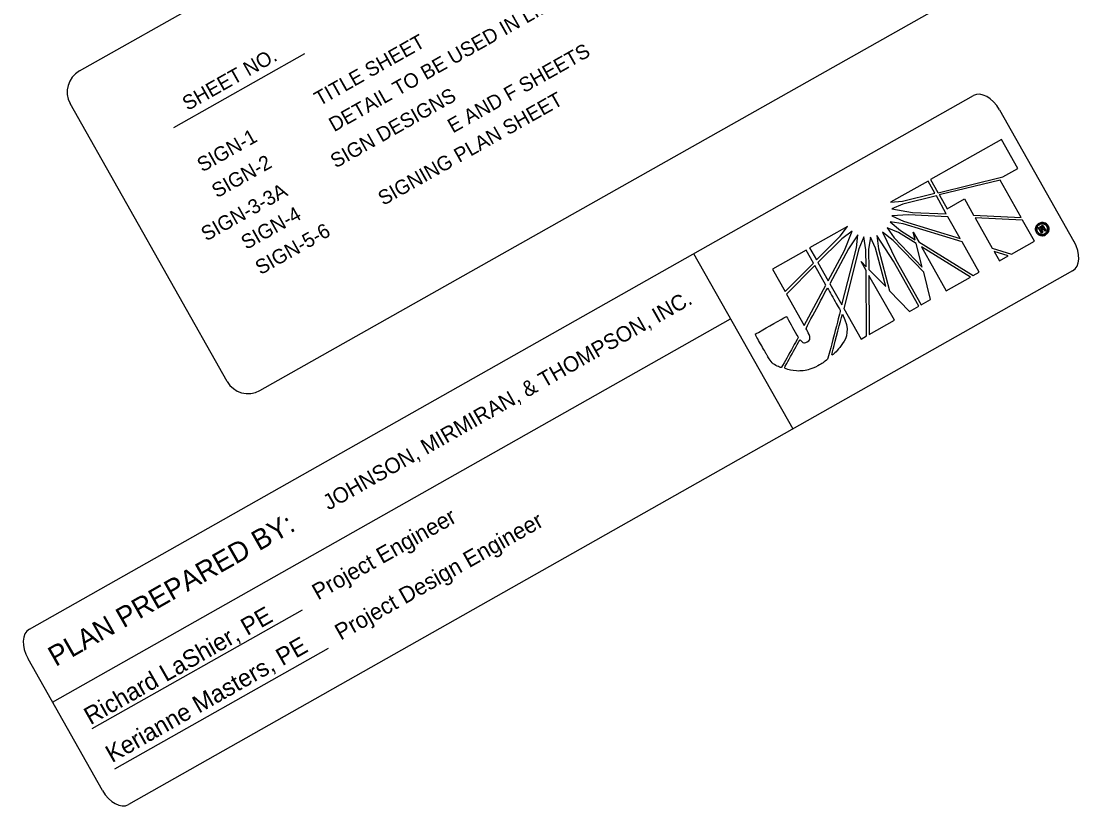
# Model space of a CAD drawing. Extents: x 2217708 to 2219063, y 217550 to 219141.
# Drawn here: x 2218577.8 to 2219063.3, y 217897.3 to 218258.3 of the extents above; entities that cross this region are included whole.
import ezdxf

# ---------------------------------------------------------------- set-up
doc = ezdxf.new("R2010")
doc.units = 0
doc.layers.add('Default', color=7, linetype='Continuous')
doc.layers.add('Sheet Title CELL', color=7, linetype='Continuous')

msp = doc.modelspace()

# ---------------------------------------------------------------- linework, layer by layer
at = {"layer": 'Default'}
for p, q in [((2218647.82, 218209.63), (2218707.74, 218243.47)), ((2218581.59, 217979.54), (2219014.14, 218224.21)), ((2219026.06, 218217.75), (2219060.22, 218157.38)), ((2219027.03, 218204.14), (2218994.51, 218185.75)), ((2219034.56, 218190.81), (2219027.03, 218204.14)), ((2218997.99, 218179.6), (2219027.65, 218186.9)), ((2219027.65, 218186.9), (2219034.56, 218190.81)), ((2218993.36, 218185), (2218976.16, 218175.37)), ((2218996.5, 218179.43), (2218993.36, 218185)), ((2218994.51, 218185.75), (2218997.89, 218179.78)), ((2219026.35, 218185.39), (2218998.51, 218178.68)), ((2219036, 218168.31), (2219026.35, 218185.39)), ((2218981.65, 218175.79), (2218996.5, 218179.43)), ((2218997.17, 218178.26), (2218981.85, 218174.42)), ((2219001.7, 218170.01), (2218997.17, 218178.26)), ((2218997.89, 218179.78), (2218997.99, 218179.6)), ((2218998.51, 218178.68), (2218998.57, 218178.58)), ((2218998.57, 218178.58), (2219002.09, 218172.35)), ((2218976.16, 218175.37), (2218981.65, 218175.79)), ((2218981.85, 218174.42), (2218976.73, 218172.33)), ((2218976.73, 218172.33), (2218986.22, 218170.69)), ((2219002.09, 218172.35), (2219010.03, 218176.84)), ((2219010.03, 218176.84), (2219014.23, 218169.41)), ((2218984.4, 218169.56), (2218976.74, 218169.17)), ((2218976.74, 218169.17), (2218982.13, 218166.59)), ((2219002.47, 218168.63), (2218984.4, 218169.56)), ((2218986.22, 218170.69), (2219001.7, 218170.01)), ((2219008.07, 218158.72), (2219002.47, 218168.63)), ((2219014.23, 218169.41), (2219036, 218168.31)), ((2219014.95, 218168.13), (2219022.77, 218154.3)), ((2219036.68, 218167.11), (2219014.95, 218168.13)), ((2218956.45, 218164.23), (2218939.04, 218154.39)), ((2218953.12, 218159.76), (2218956.45, 218164.23)), ((2218974.56, 218163.66), (2218977.87, 218159)), ((2218979.77, 218161.42), (2218974.56, 218163.66)), ((2218975.98, 218166.28), (2218980.67, 218162.39)), ((2218981.88, 218165.44), (2218975.98, 218166.28)), ((2219008.98, 218157.12), (2218981.88, 218165.44)), ((2218982.13, 218166.59), (2219008.07, 218158.72)), ((2219042.1, 218157.52), (2219036.68, 218167.11)), ((2219044.02, 218163.65), (2219044.98, 218164.19)), ((2219045.35, 218161.28), (2219044.02, 218163.65)), ((2219044.19, 218165.59), (2219044.47, 218165.09)), ((2219044.47, 218165.09), (2219044.19, 218165.59)), ((2219045.24, 218163.74), (2219044.81, 218163.5)), ((2219044.81, 218163.5), (2219045.12, 218162.94)), ((2219044.98, 218164.19), (2219045.13, 218164.28)), ((2219044.98, 218164.19), (2219045.24, 218163.74)), ((2219045.24, 218163.74), (2219044.98, 218164.19)), ((2219045.12, 218162.94), (2219045.55, 218163.18)), ((2219045.3, 218163.78), (2219045.24, 218163.74)), ((2219045.8, 218162.75), (2219045.37, 218162.51)), ((2219045.37, 218162.51), (2219045.89, 218161.58)), ((2219045.55, 218163.18), (2219045.58, 218163.19)), ((2219045.55, 218163.18), (2219045.8, 218162.75)), ((2219045.8, 218162.75), (2219045.55, 218163.18)), ((2219045.82, 218162.76), (2219045.8, 218162.75)), ((2218942.18, 218148.85), (2218953.12, 218159.76)), ((2218953.8, 218158.56), (2218942.85, 218147.65)), ((2218958.51, 218162.03), (2218953.8, 218158.56)), ((2218955.05, 218153.2), (2218958.51, 218162.03)), ((2218961.14, 218160.35), (2218956.93, 218154.03)), ((2218960.52, 218154.47), (2218961.14, 218160.35)), ((2218963.98, 218159.5), (2218961.66, 218154.01)), ((2218964.89, 218153.48), (2218963.98, 218159.5)), ((2218966.98, 218159.37), (2218966.14, 218153.71)), ((2218969.25, 218154.35), (2218966.98, 218159.37)), ((2218977.49, 218148.3), (2218969.92, 218160.13)), ((2218969.92, 218160.13), (2218970.61, 218153.98)), ((2218972.48, 218161.57), (2218978.58, 218148.92)), ((2218977.32, 218157.77), (2218972.48, 218161.57)), ((2218991.36, 218143.31), (2218977.32, 218157.77)), ((2218977.87, 218159), (2218990.71, 218145.64)), ((2218987.88, 218156.43), (2218979.77, 218161.42)), ((2218980.67, 218162.39), (2218987.46, 218158.12)), ((2218987.46, 218158.12), (2218986.52, 218161.63)), ((2218986.52, 218161.63), (2218989.08, 218157.11)), ((2219045.89, 218161.58), (2219045.35, 218161.28)), ((2219046.84, 218160.9), (2219046.86, 218160.92)), ((2219046.84, 218160.9), (2219047.13, 218160.39)), ((2219047.13, 218160.39), (2219046.84, 218160.9)), ((2219047.16, 218160.4), (2219047.13, 218160.39)), ((2218937.48, 218153.4), (2218922.01, 218144.66)), ((2218940.86, 218147.43), (2218937.48, 218153.4)), ((2218939.04, 218154.39), (2218942.18, 218148.85)), ((2218947.59, 218139.28), (2218955.05, 218153.2)), ((2218956.93, 218154.03), (2218948.35, 218137.93)), ((2218953.81, 218128.28), (2218960.52, 218154.47)), ((2218961.66, 218154.01), (2218954.73, 218126.64)), ((2218964.99, 218145.75), (2218964.89, 218153.48)), ((2218966.14, 218153.71), (2218966.24, 218144.54)), ((2218973.97, 218136.65), (2218969.25, 218154.35)), ((2218970.61, 218153.98), (2218975.69, 218134.79)), ((2218990.71, 218145.64), (2218987.88, 218156.43)), ((2218989.08, 218157.11), (2219014.1, 218141.69)), ((2219012.78, 218141.04), (2218990.33, 218154.89)), ((2218990.33, 218154.89), (2219001.71, 218134.78)), ((2219016.83, 218143.23), (2219008.98, 218157.12)), ((2219022.77, 218154.3), (2219031.61, 218151.59)), ((2219030.08, 218150.72), (2219023.62, 218152.79)), ((2219023.62, 218152.79), (2219026.08, 218148.45)), ((2219031.61, 218151.59), (2219042.1, 218157.52)), ((2218931.48, 218071.35), (2218886.01, 218151.73)), ((2218964.94, 218144.04), (2218962.63, 218148.12)), ((2218962.63, 218148.12), (2218964.99, 218145.75)), ((2218989.15, 218127.68), (2218977.49, 218148.3)), ((2218978.58, 218148.92), (2218990.25, 218128.3)), ((2219026.08, 218148.45), (2219030.08, 218150.72)), ((2219059.61, 218143.83), (2218627.06, 217899.16)), ((2218922.01, 218144.66), (2218927.81, 218134.4)), ((2218927.81, 218134.4), (2218940.86, 218147.43)), ((2218941.49, 218146.31), (2218928.48, 218133.22)), ((2218946.56, 218137.35), (2218941.49, 218146.31)), ((2218942.85, 218147.65), (2218947.59, 218139.28)), ((2218965.22, 218114.05), (2218964.94, 218144.04)), ((2218966.24, 218144.54), (2218973.97, 218136.65)), ((2218994.53, 218130.72), (2218991.36, 218143.31)), ((2219014.1, 218141.69), (2219016.83, 218143.23)), ((2218977.96, 218121.25), (2218966.2, 218141.82)), ((2218966.2, 218141.82), (2218966.42, 218114.73)), ((2219001.71, 218134.78), (2219012.78, 218141.04)), ((2218936.63, 218118.8), (2218946.56, 218137.35)), ((2218948.35, 218137.93), (2218953.81, 218128.28)), ((2218975.69, 218134.79), (2218984.91, 218125.28)), ((2218928.48, 218133.22), (2218936.63, 218118.8)), ((2218990.25, 218128.3), (2218994.53, 218130.72)), ((2218954.73, 218126.64), (2218962.67, 218112.6)), ((2218984.91, 218125.28), (2218989.15, 218127.68)), ((2218592.22, 217946.09), (2218902.88, 218121.91)), ((2218966.42, 218114.73), (2218977.96, 218121.25)), ((2218962.67, 218112.6), (2218965.22, 218114.05)), ((2218610.35, 217934.06), (2218706.7, 217988.48)), ((2218620.77, 217915.61), (2218718.69, 217970.9)), ((2218615.11, 217905.67), (2218580.95, 217966.04))]:
    msp.add_line(p, q, dxfattribs=at)
for points in [[(2219027.03, 218204.14), (2218994.51, 218185.75), (2218997.89, 218179.78), (2218997.99, 218179.6), (2219027.65, 218186.9), (2219034.56, 218190.81), (2219027.03, 218204.14)], [(2218981.65, 218175.79), (2218996.5, 218179.43), (2218993.36, 218185), (2218976.16, 218175.37), (2218981.65, 218175.79)], [(2218998.51, 218178.68), (2218998.57, 218178.58), (2219002.09, 218172.35), (2219010.03, 218176.84), (2219014.23, 218169.41), (2219036, 218168.31), (2219026.35, 218185.39), (2218998.51, 218178.68)], [(2218976.73, 218172.33), (2218986.22, 218170.69), (2219001.7, 218170.01), (2218997.17, 218178.26), (2218981.85, 218174.42), (2218976.73, 218172.33)], [(2218976.74, 218169.17), (2218982.13, 218166.59), (2219008.07, 218158.72), (2219002.47, 218168.63), (2218984.4, 218169.56), (2218976.74, 218169.17)], [(2219014.95, 218168.13), (2219022.77, 218154.3), (2219031.61, 218151.59), (2219042.1, 218157.52), (2219036.68, 218167.11), (2219014.95, 218168.13), (2219014.95, 218168.13)], [(2218953.12, 218159.76), (2218956.45, 218164.23), (2218939.04, 218154.39), (2218942.18, 218148.85), (2218953.12, 218159.76)], [(2218974.56, 218163.66), (2218977.87, 218159), (2218990.71, 218145.64), (2218987.88, 218156.43), (2218979.77, 218161.42), (2218974.56, 218163.66)], [(2218975.98, 218166.28), (2218980.67, 218162.39), (2218987.46, 218158.12), (2218986.52, 218161.63), (2218989.08, 218157.11), (2219014.1, 218141.69), (2219016.83, 218143.23), (2219008.98, 218157.12), (2218981.88, 218165.44), (2218975.98, 218166.28)], [(2219044.98, 218164.19), (2219044.02, 218163.65), (2219045.35, 218161.28), (2219045.89, 218161.58), (2219045.37, 218162.51), (2219045.8, 218162.75), (2219045.55, 218163.18), (2219045.12, 218162.94), (2219044.81, 218163.5), (2219045.24, 218163.74), (2219044.98, 218164.19)], [(2219047.04, 218162.97), (2219047.11, 218162.84), (2219047.18, 218162.77), (2219047.23, 218162.68), (2219047.44, 218162.46), (2219046.94, 218162.18)], [(2218942.85, 218147.65), (2218947.59, 218139.28), (2218955.05, 218153.2), (2218958.51, 218162.03), (2218953.8, 218158.56), (2218942.85, 218147.65)], [(2218948.35, 218137.93), (2218953.81, 218128.28), (2218960.52, 218154.47), (2218961.14, 218160.35), (2218956.93, 218154.03), (2218948.35, 218137.93)], [(2218963.98, 218159.5), (2218961.66, 218154.01), (2218954.73, 218126.64), (2218962.67, 218112.6), (2218965.22, 218114.05), (2218964.94, 218144.04), (2218962.63, 218148.12), (2218964.99, 218145.75), (2218964.89, 218153.48), (2218963.98, 218159.5)], [(2218966.98, 218159.37), (2218966.14, 218153.71), (2218966.24, 218144.54), (2218973.97, 218136.65), (2218969.25, 218154.35), (2218966.98, 218159.37)], [(2218970.61, 218153.98), (2218975.69, 218134.79), (2218984.91, 218125.28), (2218989.15, 218127.68), (2218977.49, 218148.3), (2218969.92, 218160.13), (2218970.61, 218153.98)], [(2218972.48, 218161.57), (2218978.58, 218148.92), (2218990.25, 218128.3), (2218994.53, 218130.72), (2218991.36, 218143.31), (2218977.32, 218157.77), (2218972.48, 218161.57)], [(2218927.81, 218134.4), (2218940.86, 218147.43), (2218937.48, 218153.4), (2218922.01, 218144.66), (2218927.81, 218134.4)], [(2219001.71, 218134.78), (2219012.78, 218141.04), (2218990.33, 218154.89), (2219001.71, 218134.78)], [(2219026.08, 218148.45), (2219026.08, 218148.45), (2219030.08, 218150.72), (2219023.62, 218152.79), (2219026.08, 218148.45)], [(2218936.63, 218118.8), (2218946.56, 218137.35), (2218941.49, 218146.31), (2218928.48, 218133.22), (2218936.63, 218118.8)], [(2218966.42, 218114.73), (2218977.96, 218121.25), (2218966.2, 218141.82), (2218966.42, 218114.73)]]:
    msp.add_lwpolyline(points, dxfattribs=at)
for centre, major_axis, start_param, end_param in [((2219019.8, 218214.2), (-5.65, 10.01), 4.713091, 6.283887), ((2219053.96, 218153.83), (5.65, -10.01), 0.000702, 1.571498), ((2218587.22, 217969.59), (-5.65, 10.01), 0.000702, 1.571498), ((2218621.38, 217909.21), (5.65, -10.01), 4.713091, 6.283887)]:
    msp.add_ellipse(centre, major_axis=major_axis, ratio=0.62659, start_param=start_param, end_param=end_param, dxfattribs=at)
for points, degree in [([(2219047.13, 218160.39), (2219046.43, 218159.99), (2219045.66, 218159.89), (2219044.85, 218160.12), (2219044.05, 218160.32), (2219043.44, 218160.8), (2219043.03, 218161.53), (2219042.62, 218162.26), (2219042.52, 218163.03), (2219042.77, 218163.79), (2219043.01, 218164.58), (2219043.46, 218165.18), (2219044.19, 218165.59), (2219044.19, 218165.59), (2219044.47, 218165.09), (2219044.47, 218165.09), (2219043.89, 218164.77), (2219043.51, 218164.29), (2219043.32, 218163.68), (2219043.14, 218163.04), (2219043.22, 218162.4), (2219043.54, 218161.82), (2219043.87, 218161.24), (2219044.38, 218160.84), (2219045.02, 218160.67), (2219045.66, 218160.49), (2219046.26, 218160.57), (2219046.84, 218160.9), (2219046.84, 218160.9), (2219047.13, 218160.39), (2219047.13, 218160.39), (2219047.13, 218160.39), (2219047.13, 218160.39), (2219047.13, 218160.39)], 3), ([(2219047.13, 218160.39), (2219046.43, 218159.99), (2219045.66, 218159.89), (2219044.85, 218160.12), (2219044.05, 218160.32), (2219043.44, 218160.8), (2219043.03, 218161.53), (2219042.62, 218162.26), (2219042.52, 218163.03), (2219042.77, 218163.79), (2219043.01, 218164.58), (2219043.46, 218165.18), (2219044.19, 218165.59)], 3), ([(2219044.47, 218165.09), (2219043.89, 218164.77), (2219043.51, 218164.29), (2219043.32, 218163.68), (2219043.14, 218163.04), (2219043.22, 218162.4), (2219043.54, 218161.82), (2219043.87, 218161.24), (2219044.38, 218160.84), (2219045.02, 218160.67), (2219045.66, 218160.49), (2219046.26, 218160.57), (2219046.84, 218160.9)], 3), ([(2219048.3, 218164.5), (2219048.71, 218163.77), (2219048.8, 218163), (2219048.6, 218162.21), (2219048.36, 218161.42), (2219047.89, 218160.81), (2219047.16, 218160.4), (2219047.16, 218160.4), (2219047.16, 218160.4), (2219047.13, 218160.39), (2219047.13, 218160.39), (2219046.84, 218160.9), (2219046.84, 218160.9), (2219046.86, 218160.92), (2219046.86, 218160.92), (2219046.86, 218160.92), (2219047.44, 218161.24), (2219047.83, 218161.72), (2219048.01, 218162.36), (2219048.18, 218162.99), (2219048.11, 218163.63), (2219047.78, 218164.21), (2219047.45, 218164.79), (2219046.94, 218165.19), (2219046.31, 218165.36), (2219045.68, 218165.52), (2219045.07, 218165.44), (2219044.47, 218165.09), (2219044.47, 218165.09), (2219044.19, 218165.59), (2219044.19, 218165.59), (2219044.92, 218166), (2219045.69, 218166.1), (2219046.49, 218165.89), (2219047.27, 218165.71), (2219047.88, 218165.24), (2219048.3, 218164.5), (2219048.3, 218164.5), (2219048.3, 218164.5), (2219048.3, 218164.5)], 3), ([(2219044.19, 218165.59), (2219044.92, 218166), (2219045.69, 218166.1), (2219046.49, 218165.89), (2219047.27, 218165.71), (2219047.88, 218165.24), (2219048.3, 218164.5)], 3), ([(2219046.86, 218160.92), (2219047.44, 218161.24), (2219047.83, 218161.72), (2219048.01, 218162.36), (2219048.18, 218162.99), (2219048.11, 218163.63), (2219047.78, 218164.21), (2219047.45, 218164.79), (2219046.94, 218165.19), (2219046.31, 218165.36), (2219045.68, 218165.52), (2219045.07, 218165.44), (2219044.47, 218165.09)], 3), ([(2219045.8, 218162.75), (2219045.8, 218162.75), (2219045.55, 218163.18), (2219045.55, 218163.18), (2219045.55, 218163.18), (2219045.58, 218163.19), (2219045.58, 218163.19), (2219045.92, 218163.39), (2219046.03, 218163.59), (2219045.92, 218163.79), (2219045.82, 218163.96), (2219045.62, 218163.96), (2219045.3, 218163.78), (2219045.3, 218163.78), (2219045.24, 218163.74), (2219045.24, 218163.74), (2219045.24, 218163.74), (2219044.98, 218164.19), (2219044.98, 218164.19), (2219044.98, 218164.19), (2219045.13, 218164.28), (2219045.13, 218164.28), (2219045.74, 218164.62), (2219046.17, 218164.55), (2219046.44, 218164.08), (2219046.56, 218163.86), (2219046.57, 218163.64), (2219046.45, 218163.4), (2219046.65, 218163.4), (2219046.84, 218163.26), (2219047.04, 218162.97), (2219047.04, 218162.97), (2219047.11, 218162.84), (2219047.11, 218162.84), (2219047.11, 218162.84), (2219047.18, 218162.77), (2219047.18, 218162.77), (2219047.18, 218162.77), (2219047.23, 218162.68), (2219047.23, 218162.68), (2219047.23, 218162.68), (2219047.44, 218162.46), (2219047.44, 218162.46), (2219047.44, 218162.46), (2219046.94, 218162.18), (2219046.94, 218162.18), (2219046.81, 218162.27), (2219046.69, 218162.38), (2219046.59, 218162.55), (2219046.47, 218162.76), (2219046.38, 218162.88), (2219046.28, 218162.91), (2219046.19, 218162.91), (2219046.03, 218162.88), (2219045.82, 218162.76), (2219045.82, 218162.76), (2219045.8, 218162.75), (2219045.8, 218162.75)], 3), ([(2219045.13, 218164.28), (2219045.74, 218164.62), (2219046.17, 218164.55), (2219046.44, 218164.08), (2219046.56, 218163.86), (2219046.57, 218163.64), (2219046.45, 218163.4)], 3), ([(2219045.58, 218163.19), (2219045.92, 218163.39), (2219046.03, 218163.59), (2219045.92, 218163.79), (2219045.82, 218163.96), (2219045.62, 218163.96), (2219045.3, 218163.78)], 3), ([(2219046.28, 218162.91), (2219046.19, 218162.91), (2219046.03, 218162.88), (2219045.82, 218162.76)], 2), ([(2219046.94, 218162.18), (2219046.81, 218162.27), (2219046.69, 218162.38), (2219046.59, 218162.55), (2219046.47, 218162.76), (2219046.38, 218162.88), (2219046.28, 218162.91)], 3), ([(2219046.45, 218163.4), (2219046.65, 218163.4), (2219046.84, 218163.26), (2219047.04, 218162.97)], 2), ([(2219048.3, 218164.5), (2219048.71, 218163.77), (2219048.8, 218163), (2219048.6, 218162.21), (2219048.36, 218161.42), (2219047.89, 218160.81), (2219047.16, 218160.4)], 3), ([(2218937.95, 218111.29), (2218937.03, 218110.77), (2218935.95, 218110.84), (2218934.65, 218112.36), (2218934.65, 218112.36), (2218927.43, 218099.21), (2218927.43, 218099.21), (2218932.88, 218097.55), (2218939.56, 218098.49), (2218944.18, 218101.11), (2218945.38, 218101.78), (2218946.24, 218102.4), (2218947.37, 218103.38), (2218947.37, 218103.38), (2218953.17, 218125.66), (2218953.17, 218125.66), (2218953.17, 218125.66), (2218947.28, 218136.07), (2218947.28, 218136.07), (2218947.28, 218136.07), (2218937.37, 218117.5), (2218937.37, 218117.5), (2218939.57, 218113.59), (2218939.22, 218112.01), (2218937.95, 218111.29)], 3), ([(2218937.95, 218111.29), (2218937.03, 218110.77), (2218935.95, 218110.84), (2218934.65, 218112.36), (2218934.65, 218112.36), (2218927.43, 218099.21), (2218927.43, 218099.21), (2218932.88, 218097.55), (2218939.56, 218098.49), (2218944.18, 218101.11), (2218945.38, 218101.78), (2218946.24, 218102.4), (2218947.37, 218103.38), (2218947.37, 218103.38), (2218953.17, 218125.66), (2218953.17, 218125.66), (2218953.17, 218125.66), (2218947.28, 218136.07), (2218947.28, 218136.07), (2218947.28, 218136.07), (2218937.37, 218117.5), (2218937.37, 218117.5), (2218939.57, 218113.59), (2218939.22, 218112.01), (2218937.95, 218111.29)], 3), ([(2218954.09, 218124.02), (2218954.09, 218124.02), (2218949.07, 218104.78), (2218949.07, 218104.78), (2218954.15, 218109.57), (2218957.81, 218116.79), (2218954.09, 218124.02)], 3), ([(2218954.09, 218124.02), (2218954.09, 218124.02), (2218949.07, 218104.78), (2218949.07, 218104.78), (2218954.15, 218109.57), (2218957.81, 218116.79), (2218954.09, 218124.02)], 3), ([(2218928.44, 218122.93), (2218928.44, 218122.93), (2218914.12, 218114.83), (2218914.12, 218114.83), (2218914.12, 218114.83), (2218919.18, 218105.87), (2218919.18, 218105.87), (2218919.18, 218105.87), (2218919.72, 218104.93), (2218919.72, 218104.93), (2218921.3, 218102.12), (2218923.48, 218100.42), (2218926.17, 218099.48), (2218926.17, 218099.48), (2218933.89, 218113.28), (2218933.79, 218113.46), (2218933.79, 218113.46), (2218928.44, 218122.93), (2218928.44, 218122.93)], 3), ([(2218928.44, 218122.93), (2218928.44, 218122.93), (2218914.12, 218114.83), (2218914.12, 218114.83), (2218914.12, 218114.83), (2218919.18, 218105.87), (2218919.18, 218105.87), (2218919.18, 218105.87), (2218919.72, 218104.93), (2218919.72, 218104.93), (2218921.3, 218102.12), (2218923.48, 218100.42), (2218926.17, 218099.48), (2218926.17, 218099.48), (2218933.89, 218113.28), (2218933.79, 218113.46), (2218933.79, 218113.46), (2218928.44, 218122.93), (2218928.44, 218122.93)], 3)]:
    msp.add_open_spline(points, degree=degree, dxfattribs=at)
at = {"layer": 'Sheet Title CELL'}
for p, q in [((2218604.47, 218235.5), (2218721.37, 218301.53)), ((2218687.19, 218089.02), (2219004.87, 218268.4)), ((2218672.2, 218093.19), (2218600.3, 218220.52))]:
    msp.add_line(p, q, dxfattribs=at)
for centre, start, end in [((2218609.88, 218225.93), 119.4569, 209.4569), ((2218681.78, 218098.6), 209.4569, 299.4569)]:
    msp.add_arc(centre, 11, start, end, dxfattribs=at)

# ---------------------------------------------------------------- texts
at = {"layer": 'Default'}
for s, height, rotation, p in [('SIGN-2             DETAIL TO BE USED IN LIEU OF STANDARD', 6.6381, 29.4569, (2218667.52, 218177.08)), ('SIGN-1             TITLE SHEET', 6.6381, 29.4569, (2218660.82, 218188.95)), (' E AND F SHEETS', 6.6381, 29.4569, (2218773.46, 218205.61)), ('SHEET NO.', 6.638, 29.4569, (2218654.07, 218217.13)), ('    SIGN-3-3A          SIGN DESIGNS', 6.6381, 29.4569, (2218654.05, 218152.44)), ('SIGN-5-6           SIGNING PLAN SHEET', 6.6381, 29.4569, (2218687.48, 218141.86)), ('SIGN-4          ', 6.6381, 29.4569, (2218680.98, 218153.38)), ('JOHNSON, MIRMIRAN, & THOMPSON, INC.', 7.0762, 29.6392, (2218718.69, 218033.94)), ('Project Engineer', 7.4502, 29.4569, (2218713.81, 217992.75)), ('Project Design Engineer', 7.4502, 29.4569, (2218724.22, 217974.31)), ('PLAN PREPARED BY: ', 9.2466, 29.6392, (2218593.6, 217962.26)), ('Richard LaShier, PE', 8, 29.6392, (2218609.54, 217935.55)), ('Kerianne Masters, PE', 8, 29.6392, (2218619.43, 217918.17))]:
    msp.add_text(s, height=height, rotation=rotation, dxfattribs=at).set_placement(p)

doc.saveas('drawing.dxf')
